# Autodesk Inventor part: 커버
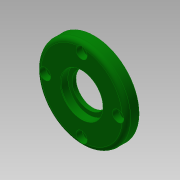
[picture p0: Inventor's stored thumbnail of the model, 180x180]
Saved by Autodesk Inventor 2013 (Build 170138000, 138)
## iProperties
Created: 2019-09
Part Number: 커버
Material: 알루미늄 6061
Document SubType Name: Modeling
Designer: mduedu
Density: 2.71 g/cm^3
Mass: 60.8493 g
Surface Area: 89.5874 cm^2
Volume: 22.4536 cm^3
Author: mduedu
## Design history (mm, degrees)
sketch "스케치1"
  geometry: C1 r 32 at (0, 0); 1 further point
  constraints: 1 centre point, 1 coincident
  dimensions: "d0" = 64 diameter of C1
extrude "돌출1" new body sketch "스케치1" distance "d1" = 9; taper "d2" = 0 deg
sketch "스케치2"
  geometry: C1 r 21 at (0, 0); 1 further point
  constraints: 1 centre point, 1 coincident
  dimensions: "d3" = 42 diameter of C1
extrude "돌출2" join sketch "스케치2" distance "d4" = 3; taper "d5" = 0 deg
hole "구멍1" diameter "d8" = 24; stored, may be unused: countersink angle "d12" = 90 deg, drill point angle "d14" = 118 deg; dims "d6" = 10, "d7" = 10, "d9" = 6, "d10" = 30, "d11" = 5.2, "d13" = 8
hole "구멍2" diameter "d17" = 37; stored, may be unused: countersink angle "d21" = 90 deg, drill point angle "d23" = 0 deg; dims "d15" = 10, "d16" = 10, "d18" = 6, "d19" = 30, "d20" = 5.2, "d22" = 4
fillet "모깎기1" dims "d24" = 3
fillet "모깎기2" dims "d25" = 3
chamfer "모따기1" distance "d27" = 0.5; stored, may be unused: second distance "d28" = 2, angle "d29" = 30 deg
chamfer "모따기2" distance "d30" = 1; stored, may be unused: second distance "d31" = 2, angle "d32" = 30 deg
sketch "스케치3" dims "d33" = 52
  geometry: 3 further points
  constraints: 2 vertical alignment, 1 coincident, 2 other
hole "구멍3" sketch "스케치3" at (0, 26) diameter "d34" = 4.5; stored, may be unused: countersink angle "d38" = 90 deg, drill point angle "d40" = 0 deg; dims "d35" = 6, "d36" = 8, "d37" = 4.4, "d39" = 4
node "솔리드1"
pattern_circular "원형 패턴1" dims angle "d42" = 360 deg
